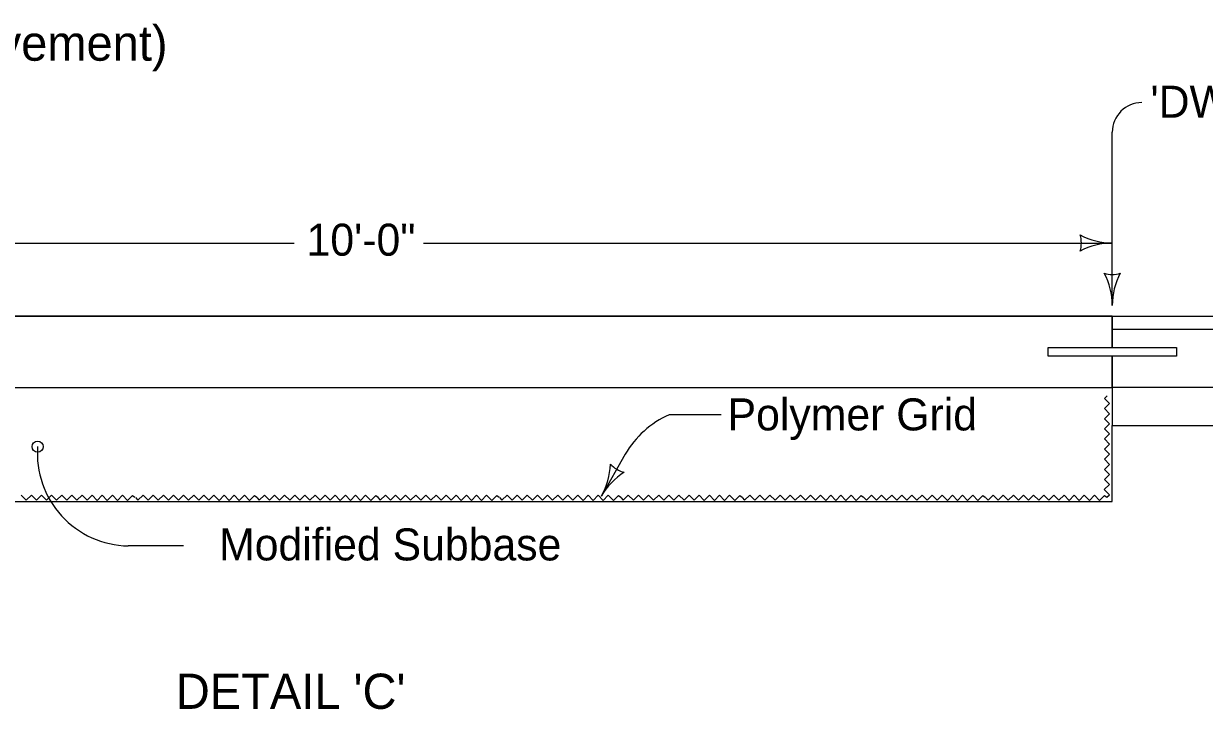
# Model space of a CAD drawing. Extents: x -2135039 to -2120895, y -2139150 to -2136566.
# Drawn here: x -2126431 to -2125693, y -2137926 to -2137497 of the extents above; entities that cross this region are included whole.
import ezdxf

# ---------------------------------------------------------------- set-up
doc = ezdxf.new("R2010")
doc.units = 0
for name, color, linetype in [('dsnStdLabel', 7, 'Continuous'), ('dsnStdLineWork', 7, 'Continuous'), ('Level 2', 7, 'Continuous'), ('Level 3', 7, 'Continuous')]:
    doc.layers.add(name, color=color, linetype=linetype)

msp = doc.modelspace()

# ---------------------------------------------------------------- linework, layer by layer
at = {"layer": 'dsnStdLabel'}
for p, q in [((-2125750.29, -2137673.14), (-2125750.29, -2137564.94)), ((-2126676.93, -2137634.17), (-2126262.05, -2137634.17)), ((-2126181.08, -2137634.17), (-2125750.29, -2137634.17)), ((-2125994.88, -2137741.51), (-2126027.56, -2137741.51)), ((-2126054.93, -2137766.23), (-2126069.91, -2137792.36)), ((-2126331.37, -2137823.49), (-2126365.93, -2137823.49))]:
    msp.add_line(p, q, dxfattribs=at)
msp.add_circle((-2126422.57, -2137761.45), 3.46, dxfattribs=at)
for centre, radius, start, end in [((-2125731.73, -2137564.93), 18.56, 90, 180), ((-2125786.14, -2137634.17), 16.51, 342.26665, 17.73335), ((-2125750.29, -2137591.42), 42.75, 241.92751, 270), ((-2125786.14, -2137634.17), 16.51, 342.26665, 17.73335), ((-2125750.29, -2137591.42), 42.75, 241.92751, 270), ((-2125750.29, -2137676.92), 42.75, 90, 118.07249), ((-2125750.29, -2137676.92), 42.75, 90, 118.07249), ((-2125750.29, -2137637.29), 16.51, 252.26665, 287.73335), ((-2125793.04, -2137673.13), 42.75, 360, 28.07249), ((-2125750.29, -2137637.29), 16.51, 252.26665, 287.73335), ((-2125793.04, -2137673.13), 42.75, 360, 28.07249), ((-2125707.55, -2137673.13), 42.75, 151.92751, 180), ((-2125707.55, -2137673.13), 42.75, 151.92751, 180), ((-2126003.4, -2137795.77), 59.4, 114.00691, 150.17827), ((-2126364.88, -2137765.66), 57.84, 175.82568, 268.95811), ((-2126107, -2137771.11), 42.75, 330.17945, 358.25194), ((-2126052.09, -2137761.27), 16.51, 222.4461, 257.9128), ((-2126032.82, -2137813.62), 42.75, 122.10696, 150.17945)]:
    msp.add_arc(centre, radius, start, end, dxfattribs=at)
at = {"layer": 'dsnStdLineWork'}
for p, q in [((-2126666.77, -2137679.93), (-2125750.29, -2137679.93)), ((-2125750.29, -2137679.93), (-2125579.49, -2137679.93)), ((-2125750.29, -2137679.93), (-2125750.29, -2137699.43)), ((-2125750.29, -2137679.93), (-2125750.29, -2137699.43)), ((-2125750.29, -2137687.98), (-2125574.56, -2137687.98)), ((-2125790.39, -2137705), (-2125790.39, -2137699.43)), ((-2125790.39, -2137699.43), (-2125710.2, -2137699.43)), ((-2125710.2, -2137699.43), (-2125710.2, -2137705)), ((-2125710.2, -2137705), (-2125790.39, -2137705)), ((-2125750.29, -2137705), (-2125750.29, -2137724.48)), ((-2126625.71, -2137724.48), (-2125750.29, -2137724.48)), ((-2125750.29, -2137724.48), (-2125750.29, -2137748.24)), ((-2125574.74, -2137724.48), (-2125750.29, -2137724.48)), ((-2125750.29, -2137760.69), (-2125750.29, -2137748.24)), ((-2125750.29, -2137748.24), (-2125579.54, -2137748.24)), ((-2125750.29, -2137795.76), (-2125750.29, -2137760.69)), ((-2126647.23, -2137795.76), (-2125750.29, -2137795.76))]:
    msp.add_line(p, q, dxfattribs=at)
for points in [[(-2125753.71, -2137793.1), (-2125752.12, -2137791.52), (-2125755.28, -2137788.34), (-2125752.11, -2137785.19), (-2125755.27, -2137782), (-2125752.08, -2137778.84), (-2125755.25, -2137775.68), (-2125752.07, -2137772.52), (-2125755.23, -2137769.33), (-2125752.05, -2137766.18), (-2125755.22, -2137763), (-2125752.04, -2137759.84), (-2125755.2, -2137756.66), (-2125752.02, -2137753.51), (-2125755.18, -2137750.32), (-2125752, -2137747.16), (-2125755.16, -2137744), (-2125751.98, -2137740.84), (-2125755.15, -2137737.66), (-2125751.97, -2137734.5), (-2125755.13, -2137731.32), (-2125753.49, -2137729.68)], [(-2126432.79, -2137791.71), (-2126429.64, -2137794.89), (-2126426.45, -2137791.73), (-2126423.29, -2137794.91), (-2126420.13, -2137791.75), (-2126416.97, -2137794.93), (-2126413.78, -2137791.76), (-2126410.63, -2137794.94), (-2126407.45, -2137791.78), (-2126404.29, -2137794.96), (-2126401.11, -2137791.8), (-2126397.96, -2137794.97), (-2126394.77, -2137791.81), (-2126391.61, -2137794.99), (-2126388.45, -2137791.83), (-2126385.29, -2137795.01), (-2126382.11, -2137791.84), (-2126378.95, -2137795.02), (-2126375.77, -2137791.86), (-2126372.61, -2137795.04), (-2126369.44, -2137791.88), (-2126366.28, -2137795.06), (-2126363.1, -2137791.89), (-2126361.68, -2137793.03)], [(-2126361.33, -2137793.28), (-2126359.75, -2137794.87), (-2126356.57, -2137791.71), (-2126353.41, -2137794.89), (-2126350.23, -2137791.73), (-2126347.07, -2137794.91), (-2126343.9, -2137791.75), (-2126340.74, -2137794.93), (-2126337.56, -2137791.76), (-2126334.41, -2137794.94), (-2126331.22, -2137791.78), (-2126328.06, -2137794.96), (-2126324.89, -2137791.8), (-2126321.73, -2137794.97), (-2126318.55, -2137791.81), (-2126315.39, -2137794.99), (-2126312.22, -2137791.83), (-2126309.06, -2137795.01), (-2126305.89, -2137791.84), (-2126302.73, -2137795.02), (-2126299.54, -2137791.86), (-2126296.39, -2137795.04), (-2126293.21, -2137791.88), (-2126290.05, -2137795.06), (-2126286.88, -2137791.89), (-2126285.45, -2137793.03)], [(-2126285.46, -2137793.28), (-2126283.88, -2137794.87), (-2126280.7, -2137791.71), (-2126277.55, -2137794.89), (-2126274.36, -2137791.73), (-2126271.2, -2137794.91), (-2126268.03, -2137791.75), (-2126264.87, -2137794.93), (-2126261.69, -2137791.76), (-2126258.54, -2137794.94), (-2126255.35, -2137791.78), (-2126252.19, -2137794.96), (-2126249.02, -2137791.8), (-2126245.87, -2137794.97), (-2126242.68, -2137791.81), (-2126239.52, -2137794.99), (-2126236.35, -2137791.83), (-2126233.19, -2137795.01), (-2126230.02, -2137791.84), (-2126226.86, -2137795.02), (-2126223.67, -2137791.86), (-2126220.52, -2137795.04), (-2126217.35, -2137791.88), (-2126214.19, -2137795.06), (-2126211.01, -2137791.89), (-2126209.58, -2137793.03)], [(-2126209.77, -2137793.28), (-2126208.2, -2137794.87), (-2126205.01, -2137791.71), (-2126201.86, -2137794.89), (-2126198.68, -2137791.73), (-2126195.52, -2137794.91), (-2126192.35, -2137791.75), (-2126189.19, -2137794.93), (-2126186, -2137791.76), (-2126182.85, -2137794.94), (-2126179.67, -2137791.78), (-2126176.51, -2137794.96), (-2126173.33, -2137791.8), (-2126170.18, -2137794.97), (-2126167, -2137791.81), (-2126163.84, -2137794.99), (-2126160.67, -2137791.83), (-2126157.51, -2137795.01), (-2126154.33, -2137791.84), (-2126151.17, -2137795.02), (-2126147.99, -2137791.86), (-2126144.84, -2137795.04), (-2126141.66, -2137791.88), (-2126138.5, -2137795.06), (-2126135.32, -2137791.89), (-2126133.9, -2137793.03)], [(-2126133.65, -2137793.28), (-2126132.07, -2137794.87), (-2126128.89, -2137791.71), (-2126125.73, -2137794.89), (-2126122.55, -2137791.73), (-2126119.39, -2137794.91), (-2126116.22, -2137791.75), (-2126113.06, -2137794.93), (-2126109.88, -2137791.76), (-2126106.73, -2137794.94), (-2126103.54, -2137791.78), (-2126100.38, -2137794.96), (-2126097.21, -2137791.8), (-2126094.05, -2137794.97), (-2126090.87, -2137791.81), (-2126087.71, -2137794.99), (-2126084.54, -2137791.83), (-2126081.38, -2137795.01), (-2126078.21, -2137791.84), (-2126075.05, -2137795.02), (-2126071.86, -2137791.86), (-2126068.71, -2137795.04), (-2126065.54, -2137791.88), (-2126062.37, -2137795.06), (-2126059.2, -2137791.89), (-2126057.77, -2137793.03)], [(-2126057.79, -2137793.28), (-2126056.21, -2137794.87), (-2126053.03, -2137791.71), (-2126049.87, -2137794.89), (-2126046.69, -2137791.73), (-2126043.53, -2137794.91), (-2126040.36, -2137791.75), (-2126037.2, -2137794.93), (-2126034.02, -2137791.76), (-2126030.86, -2137794.94), (-2126027.68, -2137791.78), (-2126024.52, -2137794.96), (-2126021.35, -2137791.8), (-2126018.19, -2137794.97), (-2126015.01, -2137791.81), (-2126011.85, -2137794.99), (-2126008.68, -2137791.83), (-2126005.52, -2137795.01), (-2126002.35, -2137791.84), (-2125999.19, -2137795.02), (-2125996, -2137791.86), (-2125992.85, -2137795.04), (-2125989.67, -2137791.88), (-2125986.51, -2137795.06), (-2125983.34, -2137791.89), (-2125981.91, -2137793.03)], [(-2125981.84, -2137793.28), (-2125980.27, -2137794.87), (-2125977.08, -2137791.71), (-2125973.93, -2137794.89), (-2125970.75, -2137791.73), (-2125967.59, -2137794.91), (-2125964.42, -2137791.75), (-2125961.26, -2137794.93), (-2125958.08, -2137791.76), (-2125954.92, -2137794.94), (-2125951.74, -2137791.78), (-2125948.58, -2137794.96), (-2125945.4, -2137791.8), (-2125942.25, -2137794.97), (-2125939.07, -2137791.81), (-2125935.91, -2137794.99), (-2125932.74, -2137791.83), (-2125929.58, -2137795.01), (-2125926.4, -2137791.84), (-2125923.24, -2137795.02), (-2125920.06, -2137791.86), (-2125916.91, -2137795.04), (-2125913.73, -2137791.88), (-2125910.57, -2137795.06), (-2125907.4, -2137791.89), (-2125905.97, -2137793.03)], [(-2125905.72, -2137793.28), (-2125904.14, -2137794.87), (-2125900.96, -2137791.71), (-2125897.81, -2137794.89), (-2125894.62, -2137791.73), (-2125891.46, -2137794.91), (-2125888.3, -2137791.75), (-2125885.14, -2137794.93), (-2125881.95, -2137791.76), (-2125878.8, -2137794.94), (-2125875.62, -2137791.78), (-2125872.46, -2137794.96), (-2125869.28, -2137791.8), (-2125866.13, -2137794.97), (-2125862.94, -2137791.81), (-2125859.78, -2137794.99), (-2125856.62, -2137791.83), (-2125853.46, -2137795.01), (-2125850.28, -2137791.84), (-2125847.12, -2137795.02), (-2125843.94, -2137791.86), (-2125840.78, -2137795.04), (-2125837.61, -2137791.88), (-2125834.45, -2137795.06), (-2125831.27, -2137791.89), (-2125829.85, -2137793.03)], [(-2125829.58, -2137793.28), (-2125828, -2137794.87), (-2125824.82, -2137791.71), (-2125821.67, -2137794.89), (-2125818.49, -2137791.73), (-2125815.33, -2137794.91), (-2125812.16, -2137791.75), (-2125809, -2137794.93), (-2125805.81, -2137791.76), (-2125802.66, -2137794.94), (-2125799.48, -2137791.78), (-2125796.32, -2137794.96), (-2125793.14, -2137791.8), (-2125789.99, -2137794.97), (-2125786.81, -2137791.81), (-2125783.65, -2137794.99), (-2125780.48, -2137791.83), (-2125777.32, -2137795.01), (-2125774.14, -2137791.84), (-2125770.98, -2137795.02), (-2125767.8, -2137791.86), (-2125764.64, -2137795.04), (-2125761.47, -2137791.88), (-2125758.31, -2137795.06), (-2125755.13, -2137791.89), (-2125753.71, -2137793.03)]]:
    msp.add_lwpolyline(points, dxfattribs=at)
at = {"layer": 'Level 2'}
for p, q in [((-2125750.3, -2137679.94), (-2126666.77, -2137679.93)), ((-2125750.3, -2137699.43), (-2125750.3, -2137679.94)), ((-2125790.39, -2137705), (-2125790.39, -2137699.43)), ((-2125790.39, -2137699.43), (-2125750.3, -2137699.43)), ((-2125750.3, -2137705), (-2125790.39, -2137705)), ((-2125750.3, -2137724.49), (-2125750.3, -2137705)), ((-2126625.71, -2137724.49), (-2125750.3, -2137724.49))]:
    msp.add_line(p, q, dxfattribs=at)

# ---------------------------------------------------------------- texts
at = {"layer": 'dsnStdLabel'}
for s, p in [("'DW' or 'RT' Joint", (-2125726.39, -2137555.83)), ('10\'-0"', (-2126254.31, -2137642.09)), ('Polymer Grid', (-2125990.94, -2137751.3)), ('Modified Subbase', (-2126309.02, -2137832.57))]:
    msp.add_text(s, height=20, dxfattribs=at).set_placement(p)
at = {"layer": 'dsnStdLineWork'}
msp.add_text('(Abutting PCC or Composite Pavement)', height=22, dxfattribs=at).set_placement((-2126862.85, -2137520.22))
at = {"layer": 'Level 3'}
msp.add_text("DETAIL 'C'", height=22, dxfattribs=at).set_placement((-2126336.08, -2137925.35))

doc.saveas('drawing.dxf')
